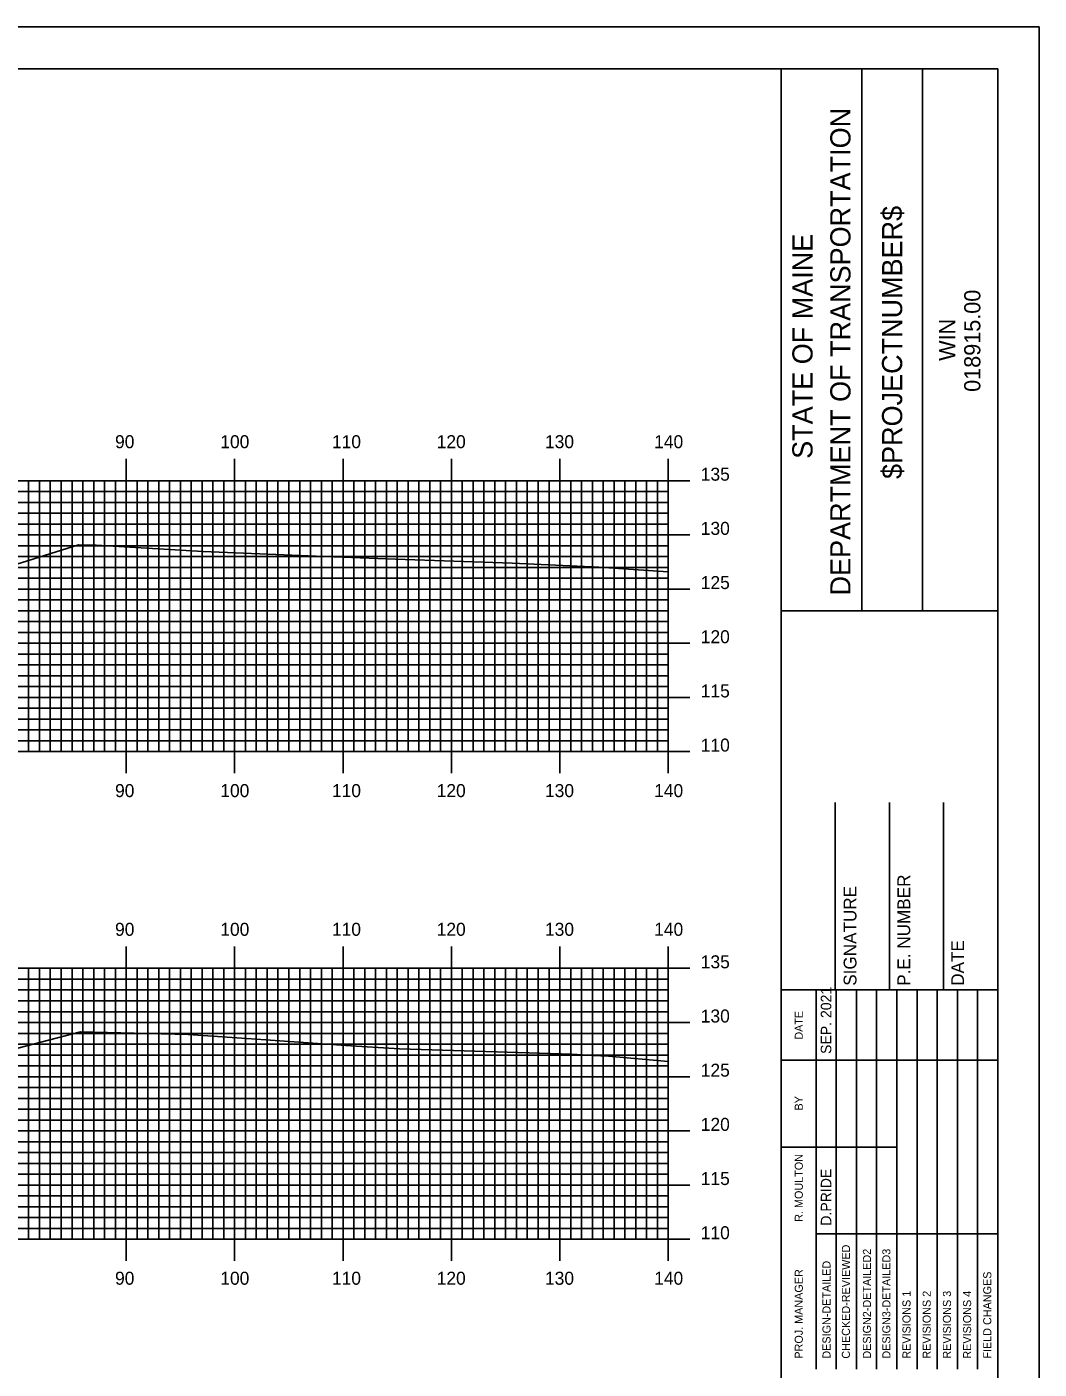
# Model space of a CAD drawing. Extents: x 842569 to 842912, y 363538 to 363758.
# Drawn here: x 842815.2 to 842908.6, y 363633.7 to 363757.6 of the extents above; entities that cross this region are included whole.
import ezdxf

# ---------------------------------------------------------------- set-up
doc = ezdxf.new("R2010")
doc.units = 0
for name, color, linetype in [('BORDER', 7, 'Continuous'), ('H_V ANNOTATION', 7, 'Continuous'), ('MAJOR', 7, 'Continuous'), ('MINOR', 7, 'Continuous'), ('PLOT BOUNDARY', 7, 'Continuous'), ('S_Roadway_Centerline', 7, 'Continuous')]:
    doc.layers.add(name, color=color, linetype=linetype)

msp = doc.modelspace()

# ---------------------------------------------------------------- linework, layer by layer
at = {"layer": 'BORDER'}
for p, q in [((842884.8, 363543.72), (842884.8, 363753.72)), ((842892.26, 363703.72), (842892.26, 363753.72)), ((842897.85, 363703.72), (842897.85, 363753.72)), ((842884.8, 363703.71), (842904.8, 363703.71)), ((842889.8, 363668.73), (842889.8, 363686.02)), ((842894.8, 363668.73), (842894.8, 363686.02)), ((842899.8, 363668.73), (842899.8, 363686.02)), ((842884.8, 363668.73), (842904.8, 363668.73))]:
    msp.add_line(p, q, dxfattribs=at)
msp.add_lwpolyline([(842584.8, 363543.72), (842904.8, 363543.72), (842904.8, 363753.72), (842584.8, 363753.72)], close=True, dxfattribs=at)
for points in [[(842888.03, 363662.23), (842888.03, 363668.73)], [(842889.89, 363633.73), (842889.89, 363668.73)], [(842891.76, 363668.73), (842891.76, 363633.73)], [(842893.62, 363633.73), (842893.62, 363668.73)], [(842895.48, 363633.73), (842895.48, 363668.73)], [(842897.35, 363633.73), (842897.35, 363668.73)], [(842899.21, 363633.73), (842899.21, 363668.73)], [(842901.07, 363633.73), (842901.07, 363668.73)], [(842902.94, 363633.73), (842902.94, 363668.73)], [(842888.03, 363633.73), (842888.03, 363667.31)], [(842884.8, 363662.23), (842904.8, 363662.23)], [(842884.8, 363654.23), (842888.03, 363654.23)], [(842888.03, 363654.23), (842895.48, 363654.23)], [(842888.03, 363646.23), (842904.8, 363646.23)]]:
    msp.add_lwpolyline(points, dxfattribs=at)
at = {"layer": 'MAJOR'}
for p, q in [((842824.4, 363717.73), (842824.4, 363715.72)), ((842834.4, 363717.73), (842834.4, 363715.72)), ((842844.4, 363717.73), (842844.4, 363715.72)), ((842854.4, 363717.73), (842854.4, 363715.72)), ((842864.4, 363717.73), (842864.4, 363715.72)), ((842874.4, 363717.73), (842874.4, 363715.72)), ((842594.4, 363715.72), (842874.4, 363715.72)), ((842594.4, 363715.72), (842874.4, 363715.72)), ((842824.4, 363690.72), (842824.4, 363715.72)), ((842834.4, 363690.72), (842834.4, 363715.72)), ((842844.4, 363690.72), (842844.4, 363715.72)), ((842854.4, 363690.72), (842854.4, 363715.72)), ((842864.4, 363690.72), (842864.4, 363715.72)), ((842876.4, 363715.72), (842872.39, 363715.72)), ((842874.4, 363690.72), (842874.4, 363715.72)), ((842874.4, 363690.72), (842874.4, 363715.72)), ((842594.4, 363710.72), (842874.4, 363710.72)), ((842876.4, 363710.72), (842872.39, 363710.72)), ((842594.4, 363705.72), (842874.4, 363705.72)), ((842876.4, 363705.72), (842872.39, 363705.72)), ((842594.4, 363700.72), (842874.4, 363700.72)), ((842876.4, 363700.72), (842872.39, 363700.72)), ((842594.4, 363695.72), (842874.4, 363695.72)), ((842876.4, 363695.72), (842872.39, 363695.72)), ((842594.4, 363690.72), (842874.4, 363690.72)), ((842594.4, 363690.72), (842874.4, 363690.72)), ((842824.4, 363688.72), (842824.4, 363690.72)), ((842834.4, 363688.72), (842834.4, 363690.72)), ((842844.4, 363688.72), (842844.4, 363690.72)), ((842854.4, 363688.72), (842854.4, 363690.72)), ((842864.4, 363688.72), (842864.4, 363690.72)), ((842876.4, 363690.72), (842872.39, 363690.72)), ((842874.4, 363688.72), (842874.4, 363690.72)), ((842824.4, 363672.73), (842824.4, 363670.72)), ((842834.4, 363672.73), (842834.4, 363670.72)), ((842844.4, 363672.73), (842844.4, 363670.72)), ((842854.4, 363672.73), (842854.4, 363670.72)), ((842864.4, 363672.73), (842864.4, 363670.72)), ((842874.4, 363672.73), (842874.4, 363670.72)), ((842594.4, 363670.72), (842874.4, 363670.72)), ((842594.4, 363670.72), (842874.4, 363670.72)), ((842824.4, 363645.72), (842824.4, 363670.72)), ((842834.4, 363645.72), (842834.4, 363670.72)), ((842844.4, 363645.72), (842844.4, 363670.72)), ((842854.4, 363645.72), (842854.4, 363670.72)), ((842864.4, 363645.72), (842864.4, 363670.72)), ((842876.4, 363670.72), (842872.39, 363670.72)), ((842874.4, 363645.72), (842874.4, 363670.72)), ((842874.4, 363645.72), (842874.4, 363670.72)), ((842594.4, 363665.72), (842874.4, 363665.72)), ((842876.4, 363665.72), (842872.39, 363665.72)), ((842594.4, 363660.72), (842874.4, 363660.72)), ((842876.4, 363660.72), (842872.39, 363660.72)), ((842594.4, 363655.72), (842874.4, 363655.72)), ((842876.4, 363655.72), (842872.39, 363655.72)), ((842594.4, 363650.72), (842874.4, 363650.72)), ((842876.4, 363650.72), (842872.39, 363650.72)), ((842594.4, 363645.72), (842874.4, 363645.72)), ((842594.4, 363645.72), (842874.4, 363645.72)), ((842824.4, 363643.72), (842824.4, 363645.72)), ((842834.4, 363643.72), (842834.4, 363645.72)), ((842844.4, 363643.72), (842844.4, 363645.72)), ((842854.4, 363643.72), (842854.4, 363645.72)), ((842864.4, 363643.72), (842864.4, 363645.72)), ((842876.4, 363645.72), (842872.39, 363645.72)), ((842874.4, 363643.72), (842874.4, 363645.72))]:
    msp.add_line(p, q, dxfattribs=at)
at = {"layer": 'MINOR'}
for p, q in [((842815.4, 363690.72), (842815.4, 363715.72)), ((842816.4, 363690.72), (842816.4, 363715.72)), ((842817.4, 363690.72), (842817.4, 363715.72)), ((842818.4, 363690.72), (842818.4, 363715.72)), ((842819.4, 363690.72), (842819.4, 363715.72)), ((842820.4, 363690.72), (842820.4, 363715.72)), ((842821.4, 363690.72), (842821.4, 363715.72)), ((842822.4, 363690.72), (842822.4, 363715.72)), ((842823.4, 363690.72), (842823.4, 363715.72)), ((842825.4, 363690.72), (842825.4, 363715.72)), ((842826.4, 363690.72), (842826.4, 363715.72)), ((842827.4, 363690.72), (842827.4, 363715.72)), ((842828.4, 363690.72), (842828.4, 363715.72)), ((842829.4, 363690.72), (842829.4, 363715.72)), ((842830.4, 363690.72), (842830.4, 363715.72)), ((842831.4, 363690.72), (842831.4, 363715.72)), ((842832.4, 363690.72), (842832.4, 363715.72)), ((842833.4, 363690.72), (842833.4, 363715.72)), ((842835.4, 363690.72), (842835.4, 363715.72)), ((842836.4, 363690.72), (842836.4, 363715.72)), ((842837.4, 363690.72), (842837.4, 363715.72)), ((842838.4, 363690.72), (842838.4, 363715.72)), ((842839.4, 363690.72), (842839.4, 363715.72)), ((842840.4, 363690.72), (842840.4, 363715.72)), ((842841.4, 363690.72), (842841.4, 363715.72)), ((842842.4, 363690.72), (842842.4, 363715.72)), ((842843.4, 363690.72), (842843.4, 363715.72)), ((842845.4, 363690.72), (842845.4, 363715.72)), ((842846.4, 363690.72), (842846.4, 363715.72)), ((842847.4, 363690.72), (842847.4, 363715.72)), ((842848.4, 363690.72), (842848.4, 363715.72)), ((842849.4, 363690.72), (842849.4, 363715.72)), ((842850.4, 363690.72), (842850.4, 363715.72)), ((842851.4, 363690.72), (842851.4, 363715.72)), ((842852.4, 363690.72), (842852.4, 363715.72)), ((842853.4, 363690.72), (842853.4, 363715.72)), ((842855.4, 363690.72), (842855.4, 363715.72)), ((842856.4, 363690.72), (842856.4, 363715.72)), ((842857.4, 363690.72), (842857.4, 363715.72)), ((842858.4, 363690.72), (842858.4, 363715.72)), ((842859.4, 363690.72), (842859.4, 363715.72)), ((842860.4, 363690.72), (842860.4, 363715.72)), ((842861.4, 363690.72), (842861.4, 363715.72)), ((842862.4, 363690.72), (842862.4, 363715.72)), ((842863.4, 363690.72), (842863.4, 363715.72)), ((842865.4, 363690.72), (842865.4, 363715.72)), ((842866.4, 363690.72), (842866.4, 363715.72)), ((842867.4, 363690.72), (842867.4, 363715.72)), ((842868.4, 363690.72), (842868.4, 363715.72)), ((842869.4, 363690.72), (842869.4, 363715.72)), ((842870.4, 363690.72), (842870.4, 363715.72)), ((842871.4, 363690.72), (842871.4, 363715.72)), ((842872.4, 363690.72), (842872.4, 363715.72)), ((842873.4, 363690.72), (842873.4, 363715.72)), ((842594.4, 363714.72), (842874.4, 363714.72)), ((842874.4, 363714.72), (842872.39, 363714.72)), ((842594.4, 363713.72), (842874.4, 363713.72)), ((842874.4, 363713.72), (842872.39, 363713.72)), ((842594.4, 363712.72), (842874.4, 363712.72)), ((842594.4, 363711.72), (842874.4, 363711.72)), ((842874.4, 363712.72), (842872.39, 363712.72)), ((842874.4, 363711.72), (842872.39, 363711.72)), ((842594.4, 363709.72), (842874.4, 363709.72)), ((842874.4, 363709.72), (842872.39, 363709.72)), ((842594.4, 363708.72), (842874.4, 363708.72)), ((842874.4, 363708.72), (842872.39, 363708.72)), ((842594.4, 363707.72), (842874.4, 363707.72)), ((842594.4, 363706.72), (842874.4, 363706.72)), ((842874.4, 363707.72), (842872.39, 363707.72)), ((842874.4, 363706.72), (842872.39, 363706.72)), ((842594.4, 363704.72), (842874.4, 363704.72)), ((842874.4, 363704.72), (842872.39, 363704.72)), ((842594.4, 363703.72), (842874.4, 363703.72)), ((842874.4, 363703.72), (842872.39, 363703.72)), ((842594.4, 363702.72), (842874.4, 363702.72)), ((842874.4, 363702.72), (842872.39, 363702.72)), ((842594.4, 363701.72), (842874.4, 363701.72)), ((842874.4, 363701.72), (842872.39, 363701.72)), ((842594.4, 363699.72), (842874.4, 363699.72)), ((842874.4, 363699.72), (842872.39, 363699.72)), ((842594.4, 363698.72), (842874.4, 363698.72)), ((842874.4, 363698.72), (842872.39, 363698.72)), ((842594.4, 363697.72), (842874.4, 363697.72)), ((842874.4, 363697.72), (842872.39, 363697.72)), ((842594.4, 363696.72), (842874.4, 363696.72)), ((842874.4, 363696.72), (842872.39, 363696.72)), ((842594.4, 363694.72), (842874.4, 363694.72)), ((842874.4, 363694.72), (842872.39, 363694.72)), ((842594.4, 363693.72), (842874.4, 363693.72)), ((842874.4, 363693.72), (842872.39, 363693.72)), ((842594.4, 363692.72), (842874.4, 363692.72)), ((842874.4, 363692.72), (842872.39, 363692.72)), ((842594.4, 363691.72), (842874.4, 363691.72)), ((842874.4, 363691.72), (842872.39, 363691.72)), ((842594.4, 363669.72), (842874.4, 363669.72)), ((842815.4, 363645.72), (842815.4, 363670.72)), ((842816.4, 363645.72), (842816.4, 363670.72)), ((842817.4, 363645.72), (842817.4, 363670.72)), ((842818.4, 363645.72), (842818.4, 363670.72)), ((842819.4, 363645.72), (842819.4, 363670.72)), ((842820.4, 363645.72), (842820.4, 363670.72)), ((842821.4, 363645.72), (842821.4, 363670.72)), ((842822.4, 363645.72), (842822.4, 363670.72)), ((842823.4, 363645.72), (842823.4, 363670.72)), ((842825.4, 363645.72), (842825.4, 363670.72)), ((842826.4, 363645.72), (842826.4, 363670.72)), ((842827.4, 363645.72), (842827.4, 363670.72)), ((842828.4, 363645.72), (842828.4, 363670.72)), ((842829.4, 363645.72), (842829.4, 363670.72)), ((842830.4, 363645.72), (842830.4, 363670.72)), ((842831.4, 363645.72), (842831.4, 363670.72)), ((842832.4, 363645.72), (842832.4, 363670.72)), ((842833.4, 363645.72), (842833.4, 363670.72)), ((842835.4, 363645.72), (842835.4, 363670.72)), ((842836.4, 363645.72), (842836.4, 363670.72)), ((842837.4, 363645.72), (842837.4, 363670.72)), ((842838.4, 363645.72), (842838.4, 363670.72)), ((842839.4, 363645.72), (842839.4, 363670.72)), ((842840.4, 363645.72), (842840.4, 363670.72)), ((842841.4, 363645.72), (842841.4, 363670.72)), ((842842.4, 363645.72), (842842.4, 363670.72)), ((842843.4, 363645.72), (842843.4, 363670.72)), ((842845.4, 363645.72), (842845.4, 363670.72)), ((842846.4, 363645.72), (842846.4, 363670.72)), ((842847.4, 363645.72), (842847.4, 363670.72)), ((842848.4, 363645.72), (842848.4, 363670.72)), ((842849.4, 363645.72), (842849.4, 363670.72)), ((842850.4, 363645.72), (842850.4, 363670.72)), ((842851.4, 363645.72), (842851.4, 363670.72)), ((842852.4, 363645.72), (842852.4, 363670.72)), ((842853.4, 363645.72), (842853.4, 363670.72)), ((842855.4, 363645.72), (842855.4, 363670.72)), ((842856.4, 363645.72), (842856.4, 363670.72)), ((842857.4, 363645.72), (842857.4, 363670.72)), ((842858.4, 363645.72), (842858.4, 363670.72)), ((842859.4, 363645.72), (842859.4, 363670.72)), ((842860.4, 363645.72), (842860.4, 363670.72)), ((842861.4, 363645.72), (842861.4, 363670.72)), ((842862.4, 363645.72), (842862.4, 363670.72)), ((842863.4, 363645.72), (842863.4, 363670.72)), ((842865.4, 363645.72), (842865.4, 363670.72)), ((842866.4, 363645.72), (842866.4, 363670.72)), ((842867.4, 363645.72), (842867.4, 363670.72)), ((842868.4, 363645.72), (842868.4, 363670.72)), ((842869.4, 363645.72), (842869.4, 363670.72)), ((842870.4, 363645.72), (842870.4, 363670.72)), ((842871.4, 363645.72), (842871.4, 363670.72)), ((842874.4, 363669.72), (842872.39, 363669.72)), ((842872.4, 363645.72), (842872.4, 363670.72)), ((842873.4, 363645.72), (842873.4, 363670.72)), ((842594.4, 363668.72), (842874.4, 363668.72)), ((842874.4, 363668.72), (842872.39, 363668.72)), ((842594.4, 363667.72), (842874.4, 363667.72)), ((842874.4, 363667.72), (842872.39, 363667.72)), ((842594.4, 363666.72), (842874.4, 363666.72)), ((842874.4, 363666.72), (842872.39, 363666.72)), ((842594.4, 363664.72), (842874.4, 363664.72)), ((842874.4, 363664.72), (842872.39, 363664.72)), ((842594.4, 363663.72), (842874.4, 363663.72)), ((842874.4, 363663.72), (842872.39, 363663.72)), ((842594.4, 363662.72), (842874.4, 363662.72)), ((842874.4, 363662.72), (842872.39, 363662.72)), ((842594.4, 363661.72), (842874.4, 363661.72)), ((842874.4, 363661.72), (842872.39, 363661.72)), ((842594.4, 363659.72), (842874.4, 363659.72)), ((842874.4, 363659.72), (842872.39, 363659.72)), ((842594.4, 363658.72), (842874.4, 363658.72)), ((842874.4, 363658.72), (842872.39, 363658.72)), ((842594.4, 363657.72), (842874.4, 363657.72)), ((842874.4, 363657.72), (842872.39, 363657.72)), ((842594.4, 363656.72), (842874.4, 363656.72)), ((842874.4, 363656.72), (842872.39, 363656.72)), ((842594.4, 363654.72), (842874.4, 363654.72)), ((842874.4, 363654.72), (842872.39, 363654.72)), ((842594.4, 363653.72), (842874.4, 363653.72)), ((842874.4, 363653.72), (842872.39, 363653.72)), ((842594.4, 363652.72), (842874.4, 363652.72)), ((842874.4, 363652.72), (842872.39, 363652.72)), ((842594.4, 363651.72), (842874.4, 363651.72)), ((842874.4, 363651.72), (842872.39, 363651.72)), ((842594.4, 363649.72), (842874.4, 363649.72)), ((842874.4, 363649.72), (842872.39, 363649.72)), ((842594.4, 363648.72), (842874.4, 363648.72)), ((842874.4, 363648.72), (842872.39, 363648.72)), ((842594.4, 363647.72), (842874.4, 363647.72)), ((842874.4, 363647.72), (842872.39, 363647.72)), ((842594.4, 363646.72), (842874.4, 363646.72)), ((842874.4, 363646.72), (842872.39, 363646.72))]:
    msp.add_line(p, q, dxfattribs=at)
at = {"layer": 'PLOT BOUNDARY'}
msp.add_lwpolyline([(842568.61, 363537.6), (842908.61, 363537.6), (842908.61, 363757.6), (842568.61, 363757.6)], close=True, dxfattribs=at)
at = {"layer": 'S_Roadway_Centerline'}
for points in [[(842801.24, 363703.93), (842819.99, 363709.79), (842821.62, 363709.78), (842831.51, 363709.2), (842841.93, 363708.75), (842849.23, 363708.49), (842859.99, 363708.11), (842868, 363707.74), (842874.4, 363707.31)], [(842809.41, 363662.06), (842820.19, 363664.87), (842830.1, 363664.61), (842832.82, 363664.42), (842837.27, 363664.13), (842844.66, 363663.61), (842849.62, 363663.29), (842865.52, 363662.79), (842867.48, 363662.69), (842868.89, 363662.61), (842874.4, 363662.11)]]:
    msp.add_lwpolyline(points, dxfattribs=at)

# ---------------------------------------------------------------- texts
at = {"layer": 'BORDER'}
for s, height, p in [('DEPARTMENT OF TRANSPORTATION', 1.8635, (842891.21, 363705.13)), ('$PROJECTNUMBER$', 1.8635, (842895.98, 363715.88)), ('STATE OF MAINE', 1.8635, (842887.71, 363717.74)), ('018915.00', 1.491, (842903.19, 363723.92)), ('WIN', 1.491, (842900.87, 363726.78)), ('SIGNATURE', 1.181, (842891.76, 363669.11)), ('P.E. NUMBER', 1.1811, (842896.72, 363669.11)), ('DATE', 1.181, (842901.68, 363669.11)), ('SEP. 2021', 0.969, (842889.44, 363662.82)), ('DATE', 0.743, (842886.81, 363664.14)), ('BY', 0.743, (842886.81, 363657.6)), ('R. MOULTON', 0.745, (842886.81, 363647.33)), ('D.PRIDE', 0.969, (842889.44, 363646.97)), ('CHECKED-REVIEWED', 0.7455, (842891.16, 363634.7)), ('DESIGN2-DETAILED2', 0.7455, (842893.1, 363634.7)), ('DESIGN3-DETAILED3', 0.7455, (842894.89, 363634.7)), ('DESIGN-DETAILED', 0.7455, (842889.37, 363634.7)), ('PROJ. MANAGER', 0.7455, (842886.81, 363634.7)), ('FIELD CHANGES', 0.7455, (842904.2, 363634.7)), ('REVISIONS 1', 0.7455, (842896.75, 363634.7)), ('REVISIONS 2', 0.7455, (842898.61, 363634.7)), ('REVISIONS 3', 0.7455, (842900.48, 363634.7)), ('REVISIONS 4', 0.7455, (842902.34, 363634.7))]:
    msp.add_text(s, height=height, rotation=90, dxfattribs=at).set_placement(p)
at = {"layer": 'H_V ANNOTATION'}
for s, p in [('90', (842823.37, 363718.72)), ('100', (842833.08, 363718.72)), ('110', (842843.38, 363718.72)), ('120', (842853.04, 363718.72)), ('130', (842863.03, 363718.72)), ('140', (842873.1, 363718.72)), ('135', (842877.4, 363715.72)), ('130', (842877.4, 363710.72)), ('125', (842877.4, 363705.72)), ('120', (842877.4, 363700.72)), ('115', (842877.4, 363695.72)), ('110', (842877.4, 363690.72)), ('90', (842823.37, 363686.52)), ('100', (842833.08, 363686.52)), ('110', (842843.38, 363686.52)), ('120', (842853.04, 363686.52)), ('130', (842863.03, 363686.52)), ('140', (842873.1, 363686.52)), ('90', (842823.37, 363673.72)), ('100', (842833.08, 363673.72)), ('110', (842843.38, 363673.72)), ('120', (842853.04, 363673.72)), ('130', (842863.03, 363673.72)), ('140', (842873.1, 363673.72)), ('135', (842877.4, 363670.72)), ('130', (842877.4, 363665.72)), ('125', (842877.4, 363660.72)), ('120', (842877.4, 363655.72)), ('115', (842877.4, 363650.72)), ('110', (842877.4, 363645.72)), ('90', (842823.37, 363641.52)), ('100', (842833.08, 363641.52)), ('110', (842843.38, 363641.52)), ('120', (842853.04, 363641.52)), ('130', (842863.03, 363641.52)), ('140', (842873.1, 363641.52))]:
    msp.add_text(s, height=1.2, dxfattribs=at).set_placement(p)

doc.saveas('drawing.dxf')
